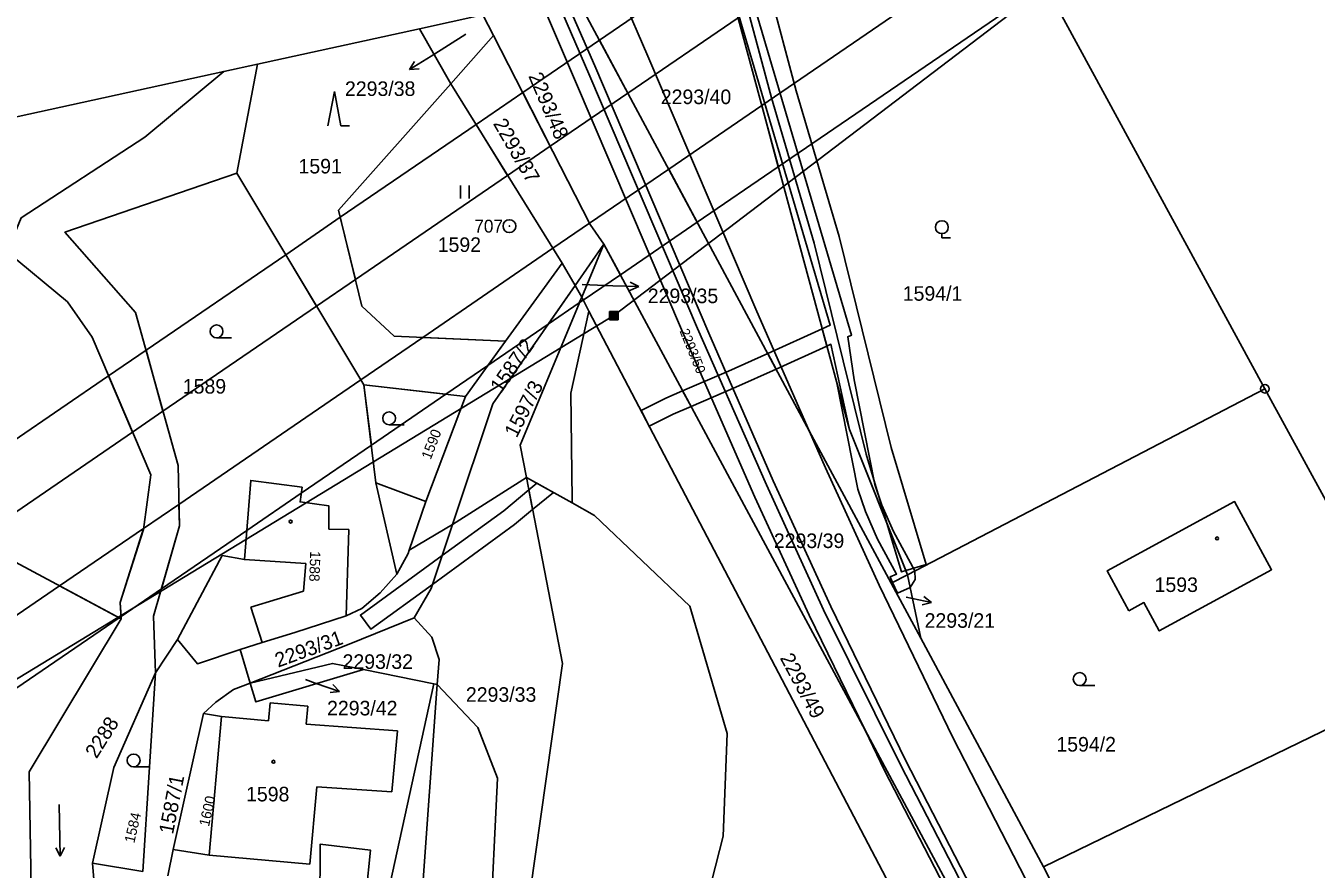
# Model space of a CAD drawing. Extents: x -504988 to -494607, y -1123820 to -1114018.
# Drawn here: x -498778.6 to -498628, y -1118304.5 to -1118206.1 of the extents above; entities that cross this region are included whole.
import ezdxf

# ---------------------------------------------------------------- set-up
doc = ezdxf.new("R2010")
doc.units = 0
for name, color, linetype in [('Hranice parcel', 7, 'Continuous'), ('Parcelní čísla', 7, 'Continuous'), ('Pop  PČ popisy', 7, 'Continuous'), ('Poz předměty', 7, 'Continuous'), ('Vnitřní kresba', 7, 'Continuous'), ('Věcná břemena k části', 7, 'Continuous'), ('Značky bodu BP', 7, 'Continuous'), ('Značky budov', 7, 'Continuous'), ('Značky kultur', 7, 'Continuous')]:
    doc.layers.add(name, color=color, linetype=linetype)

msp = doc.modelspace()

# ---------------------------------------------------------------- linework, layer by layer
at = {"layer": 'Hranice parcel'}
for p, q in [((-498633.99, -1118248.44), (-498664.92, -1118191.61)), ((-498714.54, -1118212.29), (-498718.4, -1118203.31)), ((-498716.63, -1118202.92), (-498712.74, -1118211.95)), ((-498725.25, -1118204.8), (-498732.62, -1118206.41)), ((-498723.98, -1118207.19), (-498725.25, -1118204.8)), ((-498732.62, -1118206.41), (-498751.54, -1118210.55)), ((-498728.98, -1118212.83), (-498732.62, -1118206.41)), ((-498728.98, -1118212.83), (-498723.98, -1118207.19)), ((-498755.45, -1118211.41), (-498794.15, -1118219.87)), ((-498751.54, -1118210.55), (-498755.45, -1118211.41)), ((-498753.94, -1118223.28), (-498751.54, -1118210.55)), ((-498715.99, -1118233.77), (-498728.98, -1118212.83)), ((-498739.12, -1118247.98), (-498753.94, -1118223.28)), ((-498714.48, -1118236.4), (-498711.12, -1118231.56)), ((-498713.7, -1118237.76), (-498711.12, -1118231.56)), ((-498680.64, -1118288.32), (-498711.12, -1118231.56)), ((-498722.58, -1118242.88), (-498715.99, -1118233.77)), ((-498714.48, -1118236.4), (-498715.99, -1118233.77)), ((-498713.7, -1118237.76), (-498714.48, -1118236.4)), ((-498727.26, -1118249.36), (-498722.58, -1118242.88)), ((-498727.26, -1118249.36), (-498739.12, -1118247.98)), ((-498675.69, -1118270.16), (-498633.99, -1118248.44)), ((-498615.38, -1118282.64), (-498633.99, -1118248.44)), ((-498728.78, -1118264.3), (-498720.15, -1118258.8)), ((-498733.83, -1118267.27), (-498728.78, -1118264.3)), ((-498767.41, -1118275.32), (-498782.47, -1118267.25)), ((-498677.6, -1118271.15), (-498675.69, -1118270.16)), ((-498675.69, -1118270.16), (-498674.15, -1118277.57)), ((-498677.6, -1118271.15), (-498674.15, -1118277.57)), ((-498680.64, -1118288.32), (-498687.16, -1118274.88)), ((-498763.41, -1118281.6), (-498760.85, -1118277.73)), ((-498674.15, -1118277.57), (-498659.83, -1118304.26)), ((-498752.39, -1118282.81), (-498753.53, -1118278.9)), ((-498730.34, -1118280.05), (-498730.55, -1118282.98)), ((-498764.89, -1118304.82), (-498763.41, -1118281.6)), ((-498730.55, -1118282.98), (-498732.37, -1118308.15)), ((-498659.83, -1118304.26), (-498615.38, -1118282.64)), ((-498757.82, -1118286.36), (-498761.35, -1118302.23)), ((-498678.36, -1118293.02), (-498680.64, -1118288.32)), ((-498663.08, -1118321.02), (-498680.64, -1118288.32)), ((-498761.35, -1118302.23), (-498761.99, -1118305.32)), ((-498770.78, -1118303.84), (-498764.89, -1118304.82)), ((-498659.83, -1118304.26), (-498646.54, -1118330.09))]:
    msp.add_line(p, q, dxfattribs=at)
for points in [[(-498697.21, -1118198.67), (-498682.46, -1118253.2), (-498678.1, -1118264.12), (-498675.88, -1118269.67), (-498675.69, -1118270.16)], [(-498714.47, -1118202.45), (-498687.16, -1118253.34), (-498677.6, -1118271.15)], [(-498711.12, -1118231.56), (-498712.73, -1118229.26), (-498723.98, -1118207.19)], [(-498755.45, -1118211.41), (-498764.66, -1118219.08), (-498779.1, -1118228.47), (-498780.72, -1118232.46), (-498773.68, -1118238.31), (-498770.81, -1118242.41), (-498763.98, -1118258.5), (-498764.84, -1118264.89), (-498767.53, -1118273.38), (-498767.41, -1118275.32)], [(-498722.58, -1118242.88), (-498735.56, -1118242.31), (-498739.35, -1118238.8), (-498742.06, -1118227.6), (-498728.98, -1118212.83)], [(-498687.16, -1118274.88), (-498693.48, -1118261.09), (-498701.82, -1118242.08), (-498714.54, -1118212.29)], [(-498712.74, -1118211.95), (-498700.18, -1118241.4), (-498692.12, -1118259.66), (-498685.49, -1118274.27), (-498676.51, -1118292.36), (-498665.29, -1118314.05)], [(-498763.41, -1118281.6), (-498763.64, -1118275), (-498760.63, -1118264.44), (-498760.79, -1118257.4), (-498765.76, -1118239.54), (-498774, -1118230.18), (-498753.94, -1118223.28)], [(-498714.48, -1118236.4), (-498724.08, -1118250.21), (-498728.78, -1118264.3)], [(-498713.7, -1118237.76), (-498720.89, -1118255.02), (-498720.15, -1118258.8)], [(-498667.32, -1118326.29), (-498712.85, -1118239.38), (-498713.7, -1118237.76)], [(-498735.26, -1118270.1), (-498737.7, -1118259.42), (-498739.12, -1118247.98)], [(-498733.83, -1118267.27), (-498731.88, -1118261.62), (-498727.26, -1118249.36)], [(-498741.17, -1118274.96), (-498740.88, -1118264.88), (-498743.2, -1118264.82), (-498743.22, -1118262.1), (-498746.55, -1118261.66), (-498746.32, -1118259.95), (-498752.32, -1118259.15), (-498753.05, -1118268.39), (-498755.64, -1118267.92), (-498760.85, -1118277.73)], [(-498720.15, -1118258.8), (-498715.92, -1118280.51), (-498723.48, -1118333.83)], [(-498720.15, -1118258.8), (-498714.83, -1118261.77), (-498712.21, -1118263.23), (-498701.08, -1118273.83), (-498696.71, -1118288.69), (-498697.21, -1118300.67), (-498703.33, -1118324.74), (-498700.32, -1118331.57), (-498692.93, -1118333.6), (-498680.65, -1118332.01), (-498667.32, -1118326.29)], [(-498649.87, -1118274.36), (-498648.11, -1118273.41), (-498646.32, -1118276.71), (-498633.2, -1118269.58), (-498637.53, -1118261.62), (-498652.4, -1118269.71), (-498649.87, -1118274.36)], [(-498728.78, -1118264.3), (-498731.27, -1118271.78), (-498733.23, -1118275.19)], [(-498735.26, -1118270.1), (-498733.96, -1118267.66), (-498733.83, -1118267.27)], [(-498741.17, -1118274.96), (-498739.34, -1118274.09), (-498737.2, -1118272.27), (-498735.26, -1118270.1)], [(-498784.21, -1118343.29), (-498783.58, -1118336.09), (-498775.38, -1118311.27), (-498777.94, -1118306.66), (-498778.18, -1118293.18), (-498767.41, -1118275.32)], [(-498753.53, -1118278.9), (-498750.98, -1118278.06), (-498747.17, -1118276.91), (-498741.17, -1118274.96)], [(-498752.39, -1118282.81), (-498740.82, -1118278.27), (-498733.23, -1118275.19)], [(-498733.23, -1118275.19), (-498731.2, -1118277.45), (-498730.34, -1118280.05)], [(-498760.85, -1118277.73), (-498758.53, -1118280.55), (-498753.53, -1118278.9)], [(-498752.39, -1118282.81), (-498742.77, -1118280.51), (-498739.16, -1118281.24)], [(-498770.78, -1118303.84), (-498768.3, -1118292.66), (-498763.41, -1118281.6)], [(-498739.16, -1118281.24), (-498751.71, -1118285.01), (-498752.39, -1118282.81)], [(-498730.55, -1118282.98), (-498730.96, -1118282.9), (-498739.16, -1118281.24)], [(-498752.39, -1118282.81), (-498754.31, -1118283.56), (-498756.39, -1118285.04), (-498757.82, -1118286.36)], [(-498723.48, -1118333.83), (-498724.43, -1118312.43), (-498723.54, -1118293.91), (-498725.8, -1118287.98), (-498730.55, -1118282.98)], [(-498757.82, -1118286.36), (-498755.72, -1118286.72), (-498757.17, -1118302.9), (-498761.35, -1118302.23)], [(-498663.36, -1118321.37), (-498665.54, -1118317.84), (-498678.36, -1118293.02)], [(-498744.24, -1118306.76), (-498744.21, -1118303.96), (-498744.2, -1118301.61), (-498738.35, -1118302.31), (-498738.83, -1118307.29)], [(-498773.43, -1118326.34), (-498770.1, -1118311.87), (-498770.78, -1118303.84)]]:
    msp.add_lwpolyline(points, dxfattribs=at)
at = {"layer": 'Pop  PČ popisy'}
for p, q in [((-498727.2, -1118207.03), (-498731.25, -1118209.6)), ((-498731.25, -1118209.6), (-498733.79, -1118211.19)), ((-498733.79, -1118211.19), (-498733.21, -1118210.24)), ((-498733.79, -1118211.19), (-498732.68, -1118211.08)), ((-498713.64, -1118236.29), (-498710.05, -1118236.42)), ((-498710.05, -1118236.42), (-498707.05, -1118236.52)), ((-498707.05, -1118236.52), (-498708.07, -1118236.99)), ((-498707.05, -1118236.52), (-498708.03, -1118235.99)), ((-498675.83, -1118272.78), (-498672.9, -1118273.4)), ((-498672.9, -1118273.4), (-498673.77, -1118272.71)), ((-498672.9, -1118273.4), (-498673.98, -1118273.69)), ((-498745.91, -1118282.4), (-498744.78, -1118282.8)), ((-498744.78, -1118282.8), (-498741.94, -1118283.78)), ((-498741.94, -1118283.78), (-498743.05, -1118283.92)), ((-498741.94, -1118283.78), (-498742.73, -1118282.98))]:
    msp.add_line(p, q, dxfattribs=at)
at = {"layer": 'Poz předměty'}
for p, q in [((-498709.94, -1118239.91), (-498639.61, -1118186.24)), ((-498881.92, -1118344.6), (-498709.94, -1118239.91)), ((-498710.44, -1118239.41), (-498709.44, -1118239.41)), ((-498710.44, -1118240.41), (-498710.44, -1118239.41)), ((-498710.44, -1118239.61), (-498709.44, -1118239.61)), ((-498710.44, -1118239.81), (-498709.44, -1118239.81)), ((-498710.44, -1118240.01), (-498709.44, -1118240.01)), ((-498710.44, -1118240.21), (-498709.44, -1118240.21)), ((-498710.24, -1118240.41), (-498710.24, -1118239.41)), ((-498710.04, -1118240.41), (-498710.04, -1118239.41)), ((-498709.84, -1118240.41), (-498709.84, -1118239.41)), ((-498709.64, -1118240.41), (-498709.64, -1118239.41)), ((-498709.44, -1118240.41), (-498709.44, -1118239.41)), ((-498710.44, -1118240.41), (-498709.44, -1118240.41))]:
    msp.add_line(p, q, dxfattribs=at)
at = {"layer": 'Vnitřní kresba'}
for p, q in [((-498709.54, -1118201.37), (-498705.98, -1118209.6)), ((-498712.18, -1118210.76), (-498715.66, -1118202.71)), ((-498705.98, -1118209.6), (-498693.26, -1118239.42)), ((-498698.85, -1118241.96), (-498712.18, -1118210.76)), ((-498712.85, -1118239.38), (-498714.97, -1118248.94)), ((-498693.26, -1118239.42), (-498687.16, -1118253.34)), ((-498691.36, -1118259.18), (-498698.85, -1118241.96)), ((-498714.81, -1118261.37), (-498714.97, -1118248.94)), ((-498687.16, -1118253.34), (-498685.26, -1118257.67)), ((-498685.26, -1118257.67), (-498678.98, -1118271.37)), ((-498731.88, -1118261.62), (-498737.7, -1118259.42)), ((-498684.64, -1118273.85), (-498691.36, -1118259.18)), ((-498714.83, -1118261.77), (-498714.81, -1118261.37)), ((-498745.88, -1118268.85), (-498753.05, -1118268.39)), ((-498746.15, -1118272.09), (-498745.88, -1118268.85)), ((-498678.98, -1118271.37), (-498670.4, -1118289.16)), ((-498752.29, -1118273.96), (-498746.15, -1118272.09)), ((-498750.98, -1118278.06), (-498752.29, -1118273.96)), ((-498675.93, -1118291.81), (-498684.64, -1118273.85)), ((-498736.34, -1118307.62), (-498730.96, -1118282.9)), ((-498750.24, -1118287.21), (-498750.06, -1118285.11)), ((-498750.06, -1118285.11), (-498745.64, -1118285.51)), ((-498755.72, -1118286.72), (-498750.24, -1118287.21)), ((-498745.64, -1118285.51), (-498745.83, -1118287.62)), ((-498745.83, -1118287.62), (-498735.17, -1118288.4)), ((-498735.17, -1118288.4), (-498735.86, -1118295.49)), ((-498670.4, -1118289.16), (-498661.17, -1118307.1)), ((-498666.98, -1118309.14), (-498675.93, -1118291.81)), ((-498744.62, -1118294.92), (-498745.42, -1118303.95)), ((-498735.86, -1118295.49), (-498744.62, -1118294.92)), ((-498745.42, -1118303.95), (-498757.17, -1118302.9))]:
    msp.add_line(p, q, dxfattribs=at)
at = {"layer": 'Věcná břemena k části'}
for points in [[(-498678.1, -1118264.12), (-498675.88, -1118269.67), (-498673.52, -1118268.97), (-498677.6, -1118255.32), (-498683.67, -1118230.66), (-498688.66, -1118213.67), (-498691.83, -1118201.8), (-498680.53, -1118195.02), (-498689.7, -1118197.03), (-498695.31, -1118200.4), (-498691.54, -1118214.47), (-498686.57, -1118231.44), (-498680.5, -1118256.1)], [(-498659.68, -1118201.24), (-498663.04, -1118195.06), (-498692.69, -1118215.36), (-498690.76, -1118222.52)], [(-498674.82, -1118269.71), (-498677.31, -1118265.1), (-498678.68, -1118262.02), (-498679.48, -1118259.63), (-498681.92, -1118247.41), (-498682.66, -1118242.37), (-498682.22, -1118242.17), (-498694.35, -1118201.02), (-498686.69, -1118196.37), (-498692.9, -1118197.73), (-498696.77, -1118200.08), (-498684.7, -1118241.03), (-498685.64, -1118241.45), (-498685.09, -1118243.47), (-498684.62, -1118243.25), (-498682.46, -1118253.2), (-498678.1, -1118264.12), (-498675.69, -1118270.16), (-498675.38, -1118271.63), (-498674.79, -1118270.73)], [(-498711.64, -1118207.73), (-498708.31, -1118213.93), (-498695.46, -1118205.14), (-498697.21, -1118198.67), (-498698.97, -1118199.06)], [(-498711.64, -1118207.73), (-498720.58, -1118213.85), (-498717.38, -1118220.14), (-498708.31, -1118213.93)], [(-498717.38, -1118220.14), (-498720.58, -1118213.85), (-498726.03, -1118217.58), (-498722.34, -1118223.54)], [(-498690.76, -1118222.52), (-498692.69, -1118215.36), (-498703.55, -1118222.8), (-498700.22, -1118229)], [(-498722.34, -1118223.54), (-498726.03, -1118217.58), (-498741.86, -1118228.42), (-498740.1, -1118235.7)], [(-498709.19, -1118235.15), (-498700.22, -1118229), (-498703.55, -1118222.8), (-498712.8, -1118229.13), (-498712.73, -1118229.26), (-498711.12, -1118231.56)], [(-498748.23, -1118232.79), (-498744.63, -1118238.8), (-498740.1, -1118235.7), (-498741.86, -1118228.42)], [(-498740.1, -1118235.7), (-498741.86, -1118228.42), (-498748.23, -1118232.79), (-498744.63, -1118238.8)], [(-498748.23, -1118232.79), (-498744.63, -1118238.8), (-498740.1, -1118235.7), (-498741.86, -1118228.42)], [(-498748.23, -1118232.79), (-498744.63, -1118238.8), (-498740.1, -1118235.7), (-498741.86, -1118228.42)], [(-498711.12, -1118231.56), (-498712.73, -1118229.26), (-498712.8, -1118229.13), (-498717.06, -1118232.05), (-498715.99, -1118233.77), (-498714.48, -1118236.4)], [(-498715.99, -1118233.77), (-498717.06, -1118232.05), (-498732.25, -1118242.46), (-498722.58, -1118242.88)], [(-498709.19, -1118235.15), (-498711.12, -1118231.56), (-498713.7, -1118237.76), (-498713.52, -1118238.11)], [(-498744.63, -1118238.8), (-498748.23, -1118232.79), (-498764.53, -1118243.95), (-498762.55, -1118251.07)], [(-498724.64, -1118245.72), (-498717.61, -1118240.91), (-498714.48, -1118236.4), (-498715.99, -1118233.77), (-498722.58, -1118242.88)], [(-498713.7, -1118237.76), (-498714.48, -1118236.4), (-498717.61, -1118240.91), (-498713.98, -1118238.42)], [(-498714.48, -1118236.4), (-498717.61, -1118240.91), (-498713.98, -1118238.42), (-498713.7, -1118237.76)], [(-498717.61, -1118240.91), (-498713.98, -1118238.42), (-498713.7, -1118237.76), (-498714.48, -1118236.4)], [(-498713.52, -1118238.11), (-498713.7, -1118237.76), (-498713.98, -1118238.42)], [(-498685.09, -1118243.47), (-498685.64, -1118241.45), (-498692, -1118244.33), (-498691.02, -1118246.15)], [(-498739.47, -1118247.4), (-498739.12, -1118247.98), (-498738.24, -1118255.04), (-498729.56, -1118249.09), (-498724.64, -1118245.72), (-498722.58, -1118242.88), (-498732.25, -1118242.46)], [(-498738.24, -1118255.04), (-498729.56, -1118249.09), (-498724.64, -1118245.72), (-498722.58, -1118242.88), (-498732.25, -1118242.46), (-498739.47, -1118247.4), (-498739.12, -1118247.98)], [(-498732.25, -1118242.46), (-498739.47, -1118247.4), (-498739.12, -1118247.98), (-498738.24, -1118255.04), (-498729.56, -1118249.09), (-498724.64, -1118245.72), (-498722.58, -1118242.88)], [(-498739.47, -1118247.4), (-498739.12, -1118247.98), (-498729.56, -1118249.09), (-498724.64, -1118245.72), (-498722.58, -1118242.88), (-498732.25, -1118242.46)], [(-498768.89, -1118246.93), (-498766.1, -1118253.5), (-498762.55, -1118251.07), (-498764.53, -1118243.95)], [(-498695.72, -1118248.27), (-498691.02, -1118246.15), (-498692, -1118244.33), (-498696.56, -1118246.39), (-498701.92, -1118248.69), (-498700.94, -1118250.51)], [(-498766.1, -1118253.5), (-498768.89, -1118246.93), (-498791.19, -1118262.2), (-498784.48, -1118266.09)], [(-498738.24, -1118255.04), (-498739.12, -1118247.98), (-498739.47, -1118247.4), (-498760.69, -1118261.94), (-498760.63, -1118264.44), (-498762.73, -1118271.81), (-498752.78, -1118265), (-498746.41, -1118260.63)], [(-498738.24, -1118255.04), (-498729.56, -1118249.09), (-498739.12, -1118247.98)], [(-498703.03, -1118251.4), (-498700.94, -1118250.51), (-498701.92, -1118248.69), (-498703.89, -1118249.54), (-498706.78, -1118250.97), (-498705.82, -1118252.8)], [(-498675.38, -1118271.63), (-498675.69, -1118270.16), (-498675.88, -1118269.67), (-498682.46, -1118253.2), (-498683.93, -1118247.76), (-498681.48, -1118260.17), (-498680.6, -1118262.76), (-498679.17, -1118266), (-498676.96, -1118270.09), (-498677.72, -1118270.42), (-498677.43, -1118271.06), (-498676.87, -1118272.3)], [(-498717, -1118260.56), (-498718.93, -1118259.48), (-498719.87, -1118260.26), (-498719.42, -1118262.56)], [(-498729.99, -1118267.93), (-498731.11, -1118271.3), (-498721.52, -1118264.31), (-498719.42, -1118262.56), (-498719.87, -1118260.26), (-498722.78, -1118262.69)], [(-498764.82, -1118264.77), (-498764.84, -1118264.89), (-498767.53, -1118273.38), (-498767.43, -1118275.03), (-498762.73, -1118271.81), (-498760.63, -1118264.44), (-498760.69, -1118261.94)], [(-498678.1, -1118264.12), (-498676.39, -1118269.83), (-498675.88, -1118269.67)], [(-498767.53, -1118273.38), (-498764.82, -1118264.77), (-498774.61, -1118271.46), (-498767.66, -1118275.19), (-498767.43, -1118275.03)], [(-498731.11, -1118271.3), (-498729.99, -1118267.93), (-498739.51, -1118274.86), (-498738.3, -1118276.53)], [(-498767.66, -1118275.19), (-498774.61, -1118271.46), (-498802.57, -1118290.6), (-498823.23, -1118304.74), (-498912.77, -1118381.9), (-498893.13, -1118374.2), (-498818.96, -1118310.29), (-498809.42, -1118303.76)]]:
    msp.add_lwpolyline(points, close=True, dxfattribs=at)
at = {"layer": 'Značky bodu BP'}
for centre, radius in [((-498722.13, -1118229.46), 0.75), ((-498722.13, -1118229.46), 0.03), ((-498633.99, -1118248.44), 0.5), ((-498633.99, -1118248.44), 0.0303)]:
    msp.add_circle(centre, radius, dxfattribs=at)
at = {"layer": 'Značky budov'}
for centre in [(-498747.66, -1118263.95), (-498639.57, -1118265.92), (-498749.66, -1118292)]:
    msp.add_circle(centre, 0.175, dxfattribs=at)
at = {"layer": 'Značky kultur'}
for p, q in [((-498742.55, -1118213.74), (-498743.3, -1118217.74)), ((-498741.8, -1118217.74), (-498742.55, -1118213.74)), ((-498741.8, -1118217.74), (-498740.8, -1118217.74)), ((-498727.84, -1118226.22), (-498727.84, -1118224.72)), ((-498726.84, -1118226.22), (-498726.84, -1118224.72)), ((-498671.68, -1118230.33), (-498671.68, -1118230.83)), ((-498671.68, -1118230.83), (-498670.68, -1118230.83)), ((-498756.3, -1118242.5), (-498754.55, -1118242.5)), ((-498736.17, -1118252.64), (-498734.42, -1118252.64)), ((-498655.6, -1118283.09), (-498653.85, -1118283.09)), ((-498765.98, -1118292.59), (-498764.23, -1118292.59)), ((-498774.65, -1118297), (-498774.55, -1118303)), ((-498774.55, -1118303), (-498775.06, -1118302.03)), ((-498774.55, -1118303), (-498774.06, -1118302.01))]:
    msp.add_line(p, q, dxfattribs=at)
for centre in [(-498671.68, -1118229.58), (-498756.3, -1118241.75), (-498736.17, -1118251.89), (-498655.6, -1118282.34), (-498765.98, -1118291.84)]:
    msp.add_circle(centre, 0.75, dxfattribs=at)

# ---------------------------------------------------------------- texts
at = {"layer": 'Parcelní čísla'}
for s, height, rotation, p in [('2293/48', 1.7, 293, (-498719.95, -1118211.93)), ('2293/37', 1.7, 300, (-498724.08, -1118217.49)), ('2293/50', 1.139, 292, (-498702.3, -1118241.7)), ('1587/2', 1.7, 55, (-498723.12, -1118249.06)), ('1597/3', 1.7, 63, (-498721.29, -1118254.26)), ('1590', 1.2, 69, (-498731.32, -1118256.8)), ('1588', 1.2, 268, (-498745.37, -1118267.37)), ('2293/31', 1.7, 20, (-498749.12, -1118281.01)), ('2293/49', 1.7, 298, (-498690.61, -1118279.87)), ('2288', 1.7, 58, (-498770.3, -1118291.72)), ('1587/1', 1.7, 79, (-498761.38, -1118300.53)), ('1600', 1.2, 77, (-498757.19, -1118299.62)), ('1584', 1.2, 77, (-498765.9, -1118301.55))]:
    msp.add_text(s, height=height, rotation=rotation, dxfattribs=at).set_placement(p)
for s, p in [('2293/38', (-498741.32, -1118214.26)), ('2293/40', (-498704.47, -1118215.21)), ('1591', (-498746.74, -1118223.31)), ('1592', (-498730.5, -1118232.47)), ('2293/35', (-498705.99, -1118238.45)), ('1594/1', (-498676.24, -1118238.17)), ('1589', (-498760.24, -1118249.01)), ('2293/39', (-498691.28, -1118267.04)), ('1593', (-498646.86, -1118272.17)), ('2293/21', (-498673.69, -1118276.35)), ('2293/32', (-498741.6, -1118281.15)), ('2293/33', (-498727.21, -1118284.99)), ('2293/42', (-498743.41, -1118286.58)), ('1594/2', (-498658.32, -1118290.8)), ('1598', (-498752.86, -1118296.62))]:
    msp.add_text(s, height=1.7, dxfattribs=at).set_placement(p)
at = {"layer": 'Značky bodu BP'}
msp.add_text('707', height=1.5, dxfattribs=at).set_placement((-498726.23, -1118230.21))

doc.saveas('drawing.dxf')
